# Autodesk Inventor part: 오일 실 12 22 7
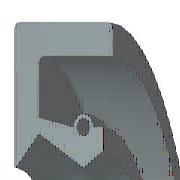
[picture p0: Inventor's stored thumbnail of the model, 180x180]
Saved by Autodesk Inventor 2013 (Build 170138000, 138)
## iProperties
IsCustomPart: 1
Created: 2012-02
Part Number: 오일 실 12 22 7
Material: 고무
Description: 오일-실
Document SubType Name: Modeling
Standard: KS B 2804
Designer: mduedu
Standards Organization: KS
Language: ko-KR
Size Designation: D - 12 22 7
Categories: <MemberInstance><Categories><Category DisplayName="샤프트 부품" InternalName="7f7aeb1f-a693-4053-b835-cee3144e0d98" Mnemonic="SHFT"><Category DisplayName="실링" Intern
Density: 0.93 g/cm^3
Mass: 1.25383 g
Surface Area: 18.4996 cm^2
Volume: 1.3482 cm^3
Author: mduedu
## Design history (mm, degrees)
revolve "본체" stored, may be unused: angle "d17" = 90 deg
revolve "스프링1" stored, may be unused: angle "d18" = 90 deg
body "Solid1"
sketch "스케치1"
  geometry: L1 (0, 11)-(7, 11); L2 (7, 9.25)-(1.75, 9.25); L3 (1.75, 7.75)-(4.9, 6); L4 (4.9, 6)-(0, 6); L5 (0, 0)-(9.586, 0) reference; L6 (4.9, 6)-(6.3, 6.875); L7 (0, 18)-(0, -3) reference; L8 (-1.941, 0)-(11.507, 0) reference; L9 (4.2, 8.1)-(1.75, 8.59); L10 (1.75, 8.59)-(1.75, 9.25); L11 (0, 11)-(0, 6.088); L12 (4.9, 6)-(0, 6); L13 (1.75, 7.75)-(0.152, 6.028); L14 (7, 11)-(7, 9.25); L15 (5.6, 8.1)-(6.3, 8.1); L16 (6.3, 8.1)-(6.3, 6.875); C1 r 0.455 at (4.9, 8.1); A1 r 0.7 centre (4.9, 8.1) between (5.6, 8.1) and (4.2, 8.1); A2 r 0.088 centre (0.088, 6.088) between (0, 6.088) and (0.152, 6.028); 1 further point
  constraints: 28 end point, 5 horizontal alignment, 5 point on line, 4 point on circle, 4 vertical alignment, 3 centre point, 3 tangent, 2 collinear, 2 horizontal, 2 perpendicular, 1 coincident, 1 parallel
  dimensions: "d0" = 22 diameter of L1 L5 (= SD2); "d1" = 1.75 distance of L1.end L2.start (= SD); "d2" = 0.91 diameter of C1 (= SPDI); "d3" = 1.4 diameter of A1 (= SPDA); "d4" = 12 diameter of L3.end L5 (= NND); "d5" = 15.5 diameter of L3.start L5 (= TKDM); "d7" = 17.18 diameter of L9.end L5 (= TKDM + 0.24 x SWDT); "d8" = 1.75 distance between parallel lines of L11 L10 (= SD); "d9" = 4.9 distance from line of L11 C1.centre (= SPDST); "d10" = 16.2 diameter of C1.centre L5 (= HLDM); "d11" = 0.0875 radius of A2 (= 0.25 x LAB); "d12" = 6.3 distance between parallel lines of L11 L16 (= SDI); "d13" = 13.75 diameter of L6.end L5 (= ABDM); "d14" = 7 distance from line of L11 L1.end (= SWDT)
fillet "모깎기1" dims "d6" = 0.3 (= RR)
other parameters: "SD2" = 22 [user parameter; used in 1 equation term], "SWDT" = 7 [user parameter; used in 2 equation terms], "RR" = 0.3 [user parameter; used in 1 equation term], "SD" = 1.75 [user parameter; used in 2 equation terms], "NND" = 12 [user parameter; used in 1 equation term], "SPDA" = 1.4 [user parameter; used in 1 equation term], "SPDI" = 0.91 [user parameter; used in 1 equation term], "TKDM" = 15.5 [user parameter; used in 2 equation terms], "HLDM" = 16.2 [user parameter; used in 1 equation term], "ABDM" = 13.75 [user parameter; used in 1 equation term], "SDI" = 6.3 [user parameter; used in 1 equation term], "SPDST" = 4.9 [user parameter; used in 1 equation term], "LAB" = 0.35 [user parameter; used in 1 equation term], "d15" = 0, "d16" = 0, "d19" = 0
